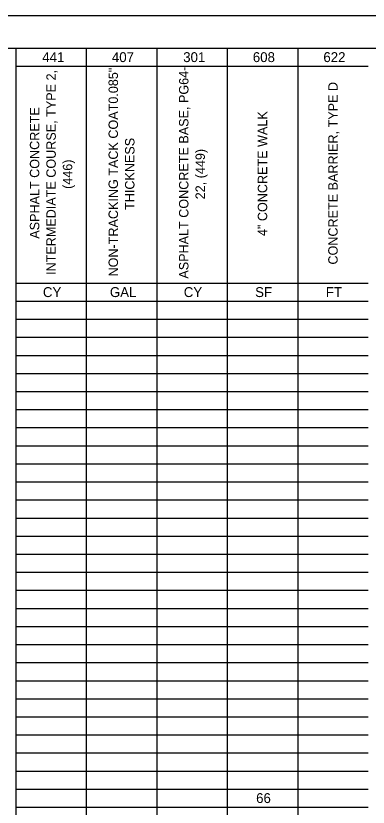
# Model space of a CAD drawing. Extents: x 0 to 34, y 0 to 22.
# Drawn here: x 20.31 to 25.76, y 9.75 to 22 of the extents above; entities that cross this region are included whole.
import ezdxf

# ---------------------------------------------------------------- set-up
doc = ezdxf.new("R2010")
doc.units = 0
for name, color, linetype in [('Default', 7, 'Continuous'), ('SH_Border', 7, 'Continuous'), ('SH_Cut_Line', 7, 'Continuous')]:
    doc.layers.add(name, color=color, linetype=linetype)

msp = doc.modelspace()

# ---------------------------------------------------------------- linework, layer by layer
at = {"layer": 'Default'}
for p, q in [((20.307, 21.5), (21.397, 21.5)), ((20.307, 21.5), (20.307, 21.22)), ((21.397, 21.5), (22.487, 21.5)), ((21.397, 21.5), (21.397, 21.22)), ((22.487, 21.5), (23.577, 21.5)), ((22.487, 21.5), (22.487, 21.22)), ((23.577, 21.5), (25.757, 21.5)), ((23.577, 21.5), (23.577, 21.22)), ((24.667, 21.5), (24.667, 21.22)), ((20.307, 21.22), (21.397, 21.22)), ((20.307, 21.22), (20.307, 20.941)), ((21.397, 21.22), (22.487, 21.22)), ((21.397, 21.22), (21.397, 20.941)), ((22.487, 21.22), (23.577, 21.22)), ((22.487, 21.22), (22.487, 20.941)), ((23.577, 21.22), (25.757, 21.22)), ((23.577, 21.22), (23.577, 20.941)), ((24.667, 21.22), (24.667, 20.941)), ((20.307, 20.941), (20.307, 20.661)), ((21.397, 20.941), (21.397, 20.661)), ((22.487, 20.941), (22.487, 20.661)), ((23.577, 20.941), (23.577, 20.661)), ((24.667, 20.941), (24.667, 20.661)), ((20.307, 20.661), (20.307, 20.381)), ((21.397, 20.661), (21.397, 20.381)), ((22.487, 20.661), (22.487, 20.381)), ((23.577, 20.661), (23.577, 20.381)), ((24.667, 20.661), (24.667, 20.381)), ((20.307, 20.381), (20.307, 20.101)), ((21.397, 20.381), (21.397, 20.101)), ((22.487, 20.381), (22.487, 20.101)), ((23.577, 20.381), (23.577, 20.101)), ((24.667, 20.381), (24.667, 20.101)), ((20.307, 20.101), (20.307, 19.822)), ((21.397, 20.101), (21.397, 19.822)), ((22.487, 20.101), (22.487, 19.822)), ((23.577, 20.101), (23.577, 19.822)), ((24.667, 20.101), (24.667, 19.822)), ((20.307, 19.822), (20.307, 19.542)), ((21.397, 19.822), (21.397, 19.542)), ((22.487, 19.822), (22.487, 19.542)), ((23.577, 19.822), (23.577, 19.542)), ((24.667, 19.822), (24.667, 19.542)), ((20.307, 19.542), (20.307, 18.982)), ((21.397, 19.542), (21.397, 18.982)), ((22.487, 19.542), (22.487, 18.982)), ((23.577, 19.542), (23.577, 18.982)), ((24.667, 19.542), (24.667, 18.982)), ((20.307, 18.982), (20.307, 18.143)), ((21.397, 18.982), (21.397, 18.143)), ((22.487, 18.982), (22.487, 18.143)), ((23.577, 18.982), (23.577, 18.143)), ((24.667, 18.982), (24.667, 18.143)), ((20.307, 18.143), (20.307, 17.864)), ((21.397, 18.143), (21.397, 17.864)), ((22.487, 18.143), (22.487, 17.864)), ((23.577, 18.143), (23.577, 17.864)), ((24.667, 18.143), (24.667, 17.864)), ((20.307, 17.864), (21.397, 17.864)), ((20.307, 17.864), (20.307, 17.304)), ((21.397, 17.864), (22.487, 17.864)), ((21.397, 17.864), (21.397, 17.304)), ((22.487, 17.864), (23.577, 17.864)), ((22.487, 17.864), (22.487, 17.304)), ((23.577, 17.864), (25.757, 17.864)), ((23.577, 17.864), (23.577, 17.304)), ((24.667, 17.864), (24.667, 17.304)), ((20.307, 17.584), (21.397, 17.584)), ((21.397, 17.584), (22.487, 17.584)), ((22.487, 17.584), (23.577, 17.584)), ((23.577, 17.584), (25.757, 17.584)), ((20.307, 17.304), (21.397, 17.304)), ((20.307, 17.304), (20.307, 17.024)), ((21.397, 17.304), (22.487, 17.304)), ((21.397, 17.304), (21.397, 17.024)), ((22.487, 17.304), (23.577, 17.304)), ((22.487, 17.304), (22.487, 17.024)), ((23.577, 17.304), (25.757, 17.304)), ((23.577, 17.304), (23.577, 17.024)), ((24.667, 17.304), (24.667, 17.024)), ((20.307, 17.024), (21.397, 17.024)), ((20.307, 17.024), (20.307, 15.905)), ((21.397, 17.024), (22.487, 17.024)), ((21.397, 17.024), (21.397, 15.905)), ((22.487, 17.024), (23.577, 17.024)), ((22.487, 17.024), (22.487, 15.905)), ((23.577, 17.024), (25.757, 17.024)), ((23.577, 17.024), (23.577, 15.905)), ((24.667, 17.024), (24.667, 15.905)), ((20.307, 16.745), (21.397, 16.745)), ((21.397, 16.745), (22.487, 16.745)), ((22.487, 16.745), (23.577, 16.745)), ((23.577, 16.745), (25.757, 16.745)), ((20.307, 16.465), (21.397, 16.465)), ((21.397, 16.465), (22.487, 16.465)), ((22.487, 16.465), (23.577, 16.465)), ((23.577, 16.465), (25.757, 16.465)), ((20.307, 16.185), (21.397, 16.185)), ((21.397, 16.185), (22.487, 16.185)), ((22.487, 16.185), (23.577, 16.185)), ((23.577, 16.185), (25.757, 16.185)), ((20.307, 15.905), (21.397, 15.905)), ((20.307, 15.905), (20.307, 15.626)), ((21.397, 15.905), (22.487, 15.905)), ((21.397, 15.905), (21.397, 15.626)), ((22.487, 15.905), (23.577, 15.905)), ((22.487, 15.905), (22.487, 15.626)), ((23.577, 15.905), (25.757, 15.905)), ((23.577, 15.905), (23.577, 15.626)), ((24.667, 15.905), (24.667, 15.626)), ((20.307, 15.626), (21.397, 15.626)), ((20.307, 15.626), (20.307, 15.066)), ((21.397, 15.626), (22.487, 15.626)), ((21.397, 15.626), (21.397, 15.066)), ((22.487, 15.626), (23.577, 15.626)), ((22.487, 15.626), (22.487, 15.066)), ((23.577, 15.626), (25.757, 15.626)), ((23.577, 15.626), (23.577, 15.066)), ((24.667, 15.626), (24.667, 15.066)), ((20.307, 15.346), (21.397, 15.346)), ((21.397, 15.346), (22.487, 15.346)), ((22.487, 15.346), (23.577, 15.346)), ((23.577, 15.346), (25.757, 15.346)), ((20.307, 15.066), (21.397, 15.066)), ((20.307, 15.066), (20.307, 14.507)), ((21.397, 15.066), (22.487, 15.066)), ((21.397, 15.066), (21.397, 14.507)), ((22.487, 15.066), (23.577, 15.066)), ((22.487, 15.066), (22.487, 14.507)), ((23.577, 15.066), (25.757, 15.066)), ((23.577, 15.066), (23.577, 14.507)), ((24.667, 15.066), (24.667, 14.507)), ((20.307, 14.786), (21.397, 14.786)), ((21.397, 14.786), (22.487, 14.786)), ((22.487, 14.786), (23.577, 14.786)), ((23.577, 14.786), (25.757, 14.786)), ((20.307, 14.507), (21.397, 14.507)), ((20.307, 14.507), (20.307, 14.227)), ((21.397, 14.507), (22.487, 14.507)), ((21.397, 14.507), (21.397, 14.227)), ((22.487, 14.507), (23.577, 14.507)), ((22.487, 14.507), (22.487, 14.227)), ((23.577, 14.507), (25.757, 14.507)), ((23.577, 14.507), (23.577, 14.227)), ((24.667, 14.507), (24.667, 14.227)), ((20.307, 14.227), (21.397, 14.227)), ((20.307, 14.227), (20.307, 13.668)), ((21.397, 14.227), (22.487, 14.227)), ((21.397, 14.227), (21.397, 13.668)), ((22.487, 14.227), (23.577, 14.227)), ((22.487, 14.227), (22.487, 13.668)), ((23.577, 14.227), (25.757, 14.227)), ((23.577, 14.227), (23.577, 13.668)), ((24.667, 14.227), (24.667, 13.668)), ((20.307, 13.947), (21.397, 13.947)), ((21.397, 13.947), (22.487, 13.947)), ((22.487, 13.947), (23.577, 13.947)), ((23.577, 13.947), (25.757, 13.947)), ((20.307, 13.668), (21.397, 13.668)), ((20.307, 13.668), (20.307, 13.388)), ((21.397, 13.668), (22.487, 13.668)), ((21.397, 13.668), (21.397, 13.388)), ((22.487, 13.668), (23.577, 13.668)), ((22.487, 13.668), (22.487, 13.388)), ((23.577, 13.668), (25.757, 13.668)), ((23.577, 13.668), (23.577, 13.388)), ((24.667, 13.668), (24.667, 13.388)), ((20.307, 13.388), (21.397, 13.388)), ((20.307, 13.388), (20.307, 12.549)), ((21.397, 13.388), (22.487, 13.388)), ((21.397, 13.388), (21.397, 12.549)), ((22.487, 13.388), (23.577, 13.388)), ((22.487, 13.388), (22.487, 12.549)), ((23.577, 13.388), (25.757, 13.388)), ((23.577, 13.388), (23.577, 12.549)), ((24.667, 13.388), (24.667, 12.549)), ((20.307, 13.108), (21.397, 13.108)), ((21.397, 13.108), (22.487, 13.108)), ((22.487, 13.108), (23.577, 13.108)), ((23.577, 13.108), (25.757, 13.108)), ((20.307, 12.828), (21.397, 12.828)), ((21.397, 12.828), (22.487, 12.828)), ((22.487, 12.828), (23.577, 12.828)), ((23.577, 12.828), (25.757, 12.828)), ((20.307, 12.549), (21.397, 12.549)), ((20.307, 12.549), (20.307, 11.989)), ((21.397, 12.549), (22.487, 12.549)), ((21.397, 12.549), (21.397, 11.989)), ((22.487, 12.549), (23.577, 12.549)), ((22.487, 12.549), (22.487, 11.989)), ((23.577, 12.549), (25.757, 12.549)), ((23.577, 12.549), (23.577, 11.989)), ((24.667, 12.549), (24.667, 11.989)), ((20.307, 12.269), (21.397, 12.269)), ((21.397, 12.269), (22.487, 12.269)), ((22.487, 12.269), (23.577, 12.269)), ((23.577, 12.269), (25.757, 12.269)), ((20.307, 11.989), (21.397, 11.989)), ((20.307, 11.989), (20.307, 11.15)), ((21.397, 11.989), (22.487, 11.989)), ((21.397, 11.989), (21.397, 11.15)), ((22.487, 11.989), (23.577, 11.989)), ((22.487, 11.989), (22.487, 11.15)), ((23.577, 11.989), (25.757, 11.989)), ((23.577, 11.989), (23.577, 11.15)), ((24.667, 11.989), (24.667, 11.15)), ((20.307, 11.709), (21.397, 11.709)), ((21.397, 11.709), (22.487, 11.709)), ((22.487, 11.709), (23.577, 11.709)), ((23.577, 11.709), (25.757, 11.709)), ((20.307, 11.43), (21.397, 11.43)), ((21.397, 11.43), (22.487, 11.43)), ((22.487, 11.43), (23.577, 11.43)), ((23.577, 11.43), (25.757, 11.43)), ((20.307, 11.15), (21.397, 11.15)), ((20.307, 11.15), (20.307, 10.591)), ((21.397, 11.15), (22.487, 11.15)), ((21.397, 11.15), (21.397, 10.591)), ((22.487, 11.15), (23.577, 11.15)), ((22.487, 11.15), (22.487, 10.591)), ((23.577, 11.15), (25.757, 11.15)), ((23.577, 11.15), (23.577, 10.591)), ((24.667, 11.15), (24.667, 10.591)), ((20.307, 10.87), (21.397, 10.87)), ((21.397, 10.87), (22.487, 10.87)), ((22.487, 10.87), (23.577, 10.87)), ((23.577, 10.87), (25.757, 10.87)), ((20.307, 10.591), (21.397, 10.591)), ((20.307, 10.591), (20.307, 9.751)), ((21.397, 10.591), (22.487, 10.591)), ((21.397, 10.591), (21.397, 9.751)), ((22.487, 10.591), (23.577, 10.591)), ((22.487, 10.591), (22.487, 9.751)), ((23.577, 10.591), (25.757, 10.591)), ((23.577, 10.591), (23.577, 9.751)), ((24.667, 10.591), (24.667, 9.751)), ((20.307, 10.311), (21.397, 10.311)), ((21.397, 10.311), (22.487, 10.311)), ((22.487, 10.311), (23.577, 10.311)), ((23.577, 10.311), (25.757, 10.311)), ((20.307, 10.031), (21.397, 10.031)), ((21.397, 10.031), (22.487, 10.031)), ((22.487, 10.031), (23.577, 10.031)), ((23.577, 10.031), (25.757, 10.031)), ((20.307, 9.751), (21.397, 9.751)), ((20.307, 9.751), (20.307, 9.192)), ((21.397, 9.751), (22.487, 9.751)), ((21.397, 9.751), (21.397, 9.192)), ((22.487, 9.751), (23.577, 9.751)), ((22.487, 9.751), (22.487, 9.192)), ((23.577, 9.751), (25.757, 9.751)), ((23.577, 9.751), (23.577, 9.192)), ((24.667, 9.751), (24.667, 9.192))]:
    msp.add_line(p, q, dxfattribs=at)
at = {"layer": 'SH_Border'}
msp.add_lwpolyline([(1.5, 21.5), (33.5, 21.5), (33.5, 0.5), (1.5, 0.5)], close=True, dxfattribs=at)
at = {"layer": 'SH_Cut_Line'}
msp.add_lwpolyline([(0, 0), (34, 0), (34, 22), (0, 22)], close=True, dxfattribs=at)

# ---------------------------------------------------------------- texts
at = {"layer": 'Default'}
for s, p in [('441', (20.716, 21.284)), ('407', (21.793, 21.284)), ('301', (22.896, 21.284)), ('608', (23.973, 21.284)), ('622', (25.064, 21.284)), ('CY', (20.726, 17.647)), ('GAL', (21.762, 17.647)), ('CY', (22.905, 17.647)), ('SF', (24.009, 17.647)), ('FT', (25.102, 17.647)), ('66', (24.024, 9.815))]:
    msp.add_text(s, height=0.1532, dxfattribs=at).set_placement(p)
for s, height, p in [('ASPHALT CONCRETE BASE, PG64-', 0.14574, (22.977, 17.932)), ('INTERMEDIATE COURSE, TYPE 2, ', 0.14574, (20.925, 17.989)), ('NON-TRACKING TACK COAT0.085" ', 0.14574, (21.887, 17.966)), ('CONCRETE BARRIER, TYPE D', 0.14574, (25.285, 18.15)), ('ASPHALT CONCRETE ', 0.14574, (20.67, 18.55)), ('4" CONCRETE WALK', 0.14574, (24.195, 18.591)), ('THICKNESS', 0.1457, (22.142, 18.996)), ('22, (449)', 0.1457, (23.232, 19.16)), ('(446)', 0.1457, (21.18, 19.321))]:
    msp.add_text(s, height=height, rotation=90, dxfattribs=at).set_placement(p)

doc.saveas('drawing.dxf')
